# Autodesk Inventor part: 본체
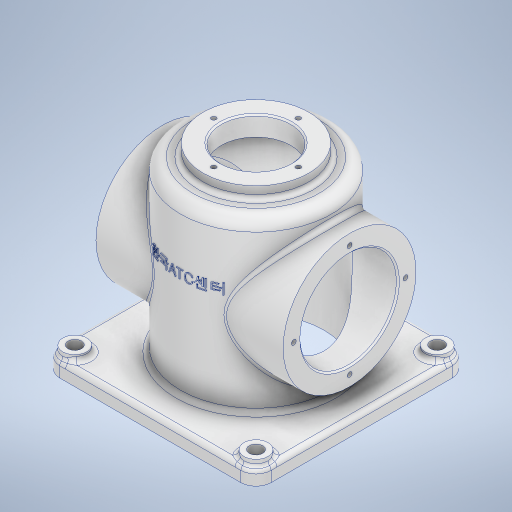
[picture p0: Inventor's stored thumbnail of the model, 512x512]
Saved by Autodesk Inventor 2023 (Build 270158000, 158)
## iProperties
Created: 2025-05
Part Number: 본체
Material: 알루미늄 6061
Document SubType Name: Modeling
Designer: User
Density: 2.7 g/cm^3
Appearance: 알루미늄 - 평지
Mass: 1130.89 g
Surface Area: 1201.45 cm^2
Volume: 418.846 cm^3
Author: User
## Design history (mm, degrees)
node "작업 평면1"
sketch "스케치2"
  geometry: L1 (-70, 70)-(70, 70); L2 (70, 70)-(70, -70); L3 (70, -70)-(-70, -70); L4 (-70, -70)-(-70, 70); L5 (-70, 70)-(70, -70); L6 (70, 70)-(-70, -70); 1 further point
  constraints: 12 end point, 2 midpoint, 2 parallel, 1 horizontal, 1 perpendicular
  dimensions: "d1" = 140 distance of L2.end L3.end; "d2" = 140 distance of L1.end L2.end
extrude "돌출1" new body sketch "스케치2" distance "d3" = 10; taper "d4" = 0 deg
sketch "스케치3"
  geometry: C1 r 50 at (0, 0); 1 further point
  constraints: 1 centre point, 1 coincident
  dimensions: "d6" = 100 diameter of C1
extrude "돌출2" join sketch "스케치3" distance "d7" = 112; taper "d8" = 0 deg
sketch "스케치4"
  geometry: C1 r 35 at (0, 0); 1 further point
  constraints: 1 centre point, 1 coincident
  dimensions: "d9" = 70 diameter of C1
extrude "돌출3" join sketch "스케치4" distance "d10" = 8; taper "d11" = 0 deg
node "작업 평면2"
sketch "스케치5"
  geometry: C1 r 44 at (0, 0); 1 further point
  constraints: 2 coincident, 1 centre point
  dimensions: "d14" = 88 diameter of C1
extrude "돌출4" join sketch "스케치5" stored distance "d15" = 8; taper "d16" = 0 deg
sketch "스케치6"
  geometry: C1 r 32 at (0, 0); 1 further point
  constraints: 1 centre point, 1 coincident
  dimensions: "d18" = 64 diameter of C1
extrude "돌출5" cut sketch "스케치6" extent not by distance; stored distance "d19" = 0; taper "d20" = 0 deg
sketch "스케치7" dims "d21" = 74
  geometry: 3 further points
  constraints: 2 vertical alignment, 1 coincident, 2 other
hole "구멍1" sketch "스케치7" at (0, 37) diameter "d22" = 3.242; stored, may be unused: countersink angle "d26" = 90 deg, drill point angle "d28" = 118 deg; dims "d23" = 8, "d24" = 4, "d25" = 2, "d27" = 10
sketch "스케치8" dims "d32" = 56
  geometry: 3 further points
  constraints: 2 horizontal alignment, 1 coincident, 2 other
hole "구멍2" sketch "스케치8" at (-28, 0) diameter "d33" = 3.242; stored, may be unused: countersink angle "d37" = 90 deg, drill point angle "d39" = 118 deg; dims "d34" = 8, "d35" = 4, "d36" = 2, "d38" = 10
sketch "스케치9"
  geometry: C1 r 23 at (0, 0); 1 further point
  constraints: 1 centre point, 1 coincident
  dimensions: "d43" = 46 diameter of C1
extrude "돌출6" cut sketch "스케치9" extent not by distance; stored distance "d44" = 0; taper "d45" = 0 deg
fillet "모깎기1" dims "d46" = 10
sketch "스케치10"
  geometry: L1 (-70, 60)-(-70, -60) reference; L2 (60, 70)-(-60, 70) reference; L3 (70, -60)-(70, 60) reference; L4 (-60, -70)-(60, -70) reference; C1 r 23 at (0, 0) reference; C2 r 8 at (-60, -60); C3 r 8 at (-60, 60); C4 r 8 at (60, -60); C5 r 8 at (60, 60); A1 r 10 centre (-60, -60) between (-70, -60) and (-60, -70) reference; A2 r 10 centre (-60, 60) between (-60, 70) and (-70, 60) reference; A3 r 10 centre (60, 60) between (70, 60) and (60, 70) reference; A4 r 10 centre (60, -60) between (60, -70) and (70, -60) reference; 1 further point
  constraints: 4 centre point, 4 coincident
  dimensions: "d47" = 16 diameter of C2; "d48" = 16 diameter of C3; "d49" = 16 diameter of C4; "d50" = 16 diameter of C5
extrude "돌출7" join sketch "스케치10" distance "d51" = 4; taper "d52" = 0 deg
sketch "스케치11"
  geometry: L1 (-120, -10)-(0, -10) reference; L2 (10, 0)-(10, 120) reference; L3 (0, 130)-(-120, 130) reference; L4 (-130, 120)-(-130, 0) reference; C1 r 8 at (0, 120) reference; C2 r 8 at (0, 0) reference; C3 r 8 at (-120, 120) reference; C4 r 8 at (-120, 0) reference; C5 r 50 at (-60, 60) reference; C6 r 8 at (-120, 0) reference; A1 r 10 centre (-120, 0) between (-130, 0) and (-120, -10) reference; A2 r 10 centre (0, 0) between (0, -10) and (10, 0) reference; A3 r 10 centre (0, 120) between (10, 120) and (0, 130) reference; A4 r 10 centre (-120, 120) between (-120, 130) and (-130, 120) reference; 5 further points
  constraints: 4 coincident
hole "구멍3" sketch "스케치11" at (-120, 0), (0, 0), (0, 120), (-120, 120) diameter "d53" = 9; stored, may be unused: countersink angle "d57" = 90 deg, drill point angle "d59" = 118 deg; dims "d54" = 8, "d55" = 4, "d56" = 2, "d58" = 10
sketch "스케치13"
  geometry: L1 (-55, 50)-(57, 50) reference; L2 (-55, -50)-(57, -50) reference; L3 (57, -50)-(57, 50) reference; L4 (-55, 45)-(52, 45); L5 (52, 45)-(52, 0); L6 (-55, -60)-(-55, 60) reference; L7 (-55, 0)-(52, 0); L8 (-91, 0)-(91, 0) reference; L9 (-55, 45)-(-65, 45); L10 (-65, -60)-(-65, 60) reference; L11 (-65, -23)-(-65, 23) reference; L12 (-55, 0)-(-65, 0); L13 (-65, 45)-(-65, 0); 1 further point
  constraints: 12 end point, 2 midpoint, 2 point on line, 1 collinear, 1 horizontal
  dimensions: "d63" = 5 distance between parallel lines of L3 L5; "d67" = 5 distance between parallel lines of L1 L4
revolve "회전1" sketch "스케치13" stored, may be unused: angle "d64" = 90 deg
fillet "모깎기4" dims "d68" = 8
fillet "모깎기5" dims "d69" = 3
fillet "모깎기6" dims "d70" = 3
chamfer "모따기1" distance "d71" = 1; stored, may be unused: second distance "d72" = 2, angle "d73" = 45 deg
fillet "모깎기7" dims "d74" = 3
fillet "모깎기8" dims "d75" = 3
node "작업 평면3"
sketch "스케치14"
  geometry: L1 (-65, 60)-(-65, -60) reference; 2 further points
  constraints: 1 horizontal alignment, 1 other
  dimensions: "d77" = 80 distance from line of L1 point (15, 0)
feature "엠보싱1" sketch "스케치14" dims "d1" = 140, "d2" = 140, "d78" = 0.5, "d79" = 0
fillet "모깎기9" dims "d80" = 3
node "솔리드1"
mirror "미러1"
pattern_circular "원형 패턴1" dims angle "d30" = 360 deg
mirror "미러2"
pattern_circular "원형 패턴2" dims angle "d41" = 360 deg
node "투영된 루프1"
node "투영된 루프2"
feature "A9D066F2-1C7D-4E18-AEED-F7BC21143FA4" dims "d53" = 9, "d54" = 8, "d55" = 4, "d56" = 2, "d57" = 90 deg, "d58" = 10, "d59" = 118 deg
other parameters: "d0" = -65, "d12" = 62, "d76" = 102.25
